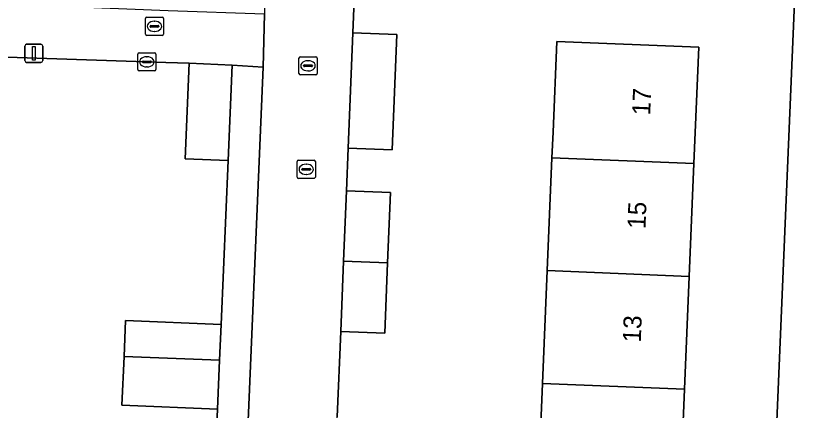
# Model space of a CAD drawing. Extents: x 161354 to 162026, y 386504 to 387460.
# Drawn here: x 161513.06 to 161556.22, y 386723.13 to 386744.88 of the extents above; entities that cross this region are included whole.
import ezdxf

# ---------------------------------------------------------------- set-up
doc = ezdxf.new("R2010")
doc.units = 0
for name, color, linetype in [('IMGEO_Brandkraan', 7, 'Continuous'), ('IMGEO_Erf', 7, 'Continuous'), ('IMGEO_Kolk', 7, 'Continuous'), ('IMGEO_Lichtmast', 7, 'Continuous'), ('IMGEO_Pand', 7, 'Continuous'), ('IMGEO_Pand_nummerreeks', 7, 'Continuous'), ('IMGEO_Rijbaan_lokaal_open', 7, 'Continuous'), ('IMGEO_Rioolput', 7, 'Continuous'), ('IMGEO_Voetpad_open', 7, 'Continuous')]:
    doc.layers.add(name, color=color, linetype=linetype)

msp = doc.modelspace()

# ---------------------------------------------------------------- linework, layer by layer
at = {"layer": 'IMGEO_Brandkraan'}
for p, q in [((161520.21, 386743.865), (161520.21, 386744.717)), ((161520.285, 386744.791), (161521.137, 386744.791)), ((161521.211, 386744.717), (161521.211, 386743.865)), ((161520.469, 386744.285), (161520.469, 386744.297)), ((161520.907, 386744.248), (161520.509, 386744.248)), ((161520.512, 386744.334), (161520.91, 386744.334)), ((161520.698, 386744.571), (161520.723, 386744.571)), ((161520.953, 386744.297), (161520.953, 386744.285)), ((161521.137, 386743.791), (161520.285, 386743.791)), ((161520.721, 386744.011), (161520.696, 386744.011))]:
    msp.add_line(p, q, dxfattribs=at)
for points in [[(161520.21, 386743.865), (161520.21, 386744.717)], [(161520.285, 386744.791), (161521.137, 386744.791)], [(161521.211, 386744.717), (161521.211, 386743.865)], [(161521.137, 386743.791), (161520.285, 386743.791)]]:
    msp.add_lwpolyline(points, dxfattribs=at)
for centre, radius, start, end in [((161520.287, 386744.715), 0.0765, 91.552, 178.448), ((161520.287, 386744.715), 0.0765, 91.552, 178.448), ((161521.135, 386744.715), 0.0765, 1.552, 88.448), ((161521.135, 386744.715), 0.0765, 1.552, 88.448), ((161520.509, 386744.294), 0.0403, 85.8775, 175.7526), ((161520.506, 386744.284), 0.0366, 178.938, 274.7102), ((161520.91, 386744.291), 0.043, 264.8664, 352.4533), ((161520.914, 386744.296), 0.0386, 1.7309, 96.639), ((161520.287, 386743.867), 0.0765, 181.552, 268.448), ((161520.287, 386743.867), 0.0765, 181.552, 268.448), ((161521.135, 386743.867), 0.0765, 271.552, 358.448), ((161521.135, 386743.867), 0.0765, 271.552, 358.448)]:
    msp.add_arc(centre, radius, start, end, dxfattribs=at)
for centre, major_axis, ratio, start_param, end_param in [((161520.697, 386744.291), (-0.387, 0.002), 0.722429, 4.712389, 7.853982), ((161520.722, 386744.291), (-0.39, 0.002), 0.717154, 1.570796, 4.712389)]:
    msp.add_ellipse(centre, major_axis=major_axis, ratio=ratio, start_param=start_param, end_param=end_param, dxfattribs=at)
at = {"layer": 'IMGEO_Erf'}
for points in [[(161553.534, 386686.819), (161556.007, 386745.625), (161531.769, 386746.655), (161531.657, 386743.931), (161534.086, 386743.832), (161533.827, 386737.476), (161531.398, 386737.577), (161531.302, 386735.23), (161533.731, 386735.129), (161533.572, 386731.252), (161533.414, 386727.375), (161530.986, 386727.476), (161530.794, 386722.78)], [(161541.863, 386718.402), (161542.12, 386724.618), (161542.377, 386730.835), (161542.635, 386737.052), (161542.693, 386738.462), (161542.9, 386743.457), (161550.725, 386743.133), (161550.46, 386736.728), (161550.202, 386730.511), (161549.945, 386724.294), (161549.688, 386718.078)], [(161496.538, 386689.04), (161520.399, 386688.074), (161520.597, 386692.953), (161522.87, 386692.861), (161523.157, 386699.22), (161518.043, 386699.418), (161518.138, 386701.89), (161518.218, 386703.953), (161523.332, 386703.755), (161523.69, 386711.288), (161518.532, 386711.505), (161518.637, 386713.996), (161518.724, 386716.073), (161523.882, 386715.856), (161524.182, 386723.194), (161518.919, 386723.421), (161519.035, 386726.105), (161519.121, 386728.084), (161524.383, 386727.857), (161524.785, 386736.896), (161522.407, 386736.993), (161522.622, 386742.251), (161521.337, 386742.294), (161500, 386743.01)]]:
    msp.add_lwpolyline(points, dxfattribs=at)
at = {"layer": 'IMGEO_Kolk'}
for p, q in [((161519.793, 386741.904), (161519.793, 386742.756)), ((161519.868, 386742.83), (161520.72, 386742.83)), ((161520.281, 386742.61), (161520.306, 386742.61)), ((161520.794, 386742.756), (161520.794, 386741.904)), ((161520.052, 386742.324), (161520.052, 386742.336)), ((161520.49, 386742.287), (161520.092, 386742.287)), ((161520.095, 386742.373), (161520.493, 386742.373)), ((161520.536, 386742.336), (161520.536, 386742.324)), ((161520.72, 386741.83), (161519.868, 386741.83)), ((161520.304, 386742.05), (161520.279, 386742.05)), ((161528.658, 386736.911), (161529.51, 386736.911)), ((161528.583, 386735.985), (161528.583, 386736.837)), ((161528.885, 386736.454), (161529.283, 386736.454)), ((161529.071, 386736.691), (161529.096, 386736.691)), ((161529.584, 386736.837), (161529.584, 386735.985)), ((161528.842, 386736.405), (161528.842, 386736.417)), ((161529.28, 386736.368), (161528.882, 386736.368)), ((161529.094, 386736.131), (161529.069, 386736.131)), ((161529.326, 386736.417), (161529.326, 386736.405)), ((161529.51, 386735.911), (161528.658, 386735.911))]:
    msp.add_line(p, q, dxfattribs=at)
for points in [[(161519.793, 386741.904), (161519.793, 386742.756)], [(161519.868, 386742.83), (161520.72, 386742.83)], [(161520.794, 386742.756), (161520.794, 386741.904)], [(161520.72, 386741.83), (161519.868, 386741.83)], [(161528.658, 386736.911), (161529.51, 386736.911)], [(161528.583, 386735.985), (161528.583, 386736.837)], [(161529.584, 386736.837), (161529.584, 386735.985)], [(161529.51, 386735.911), (161528.658, 386735.911)]]:
    msp.add_lwpolyline(points, dxfattribs=at)
for centre, radius, start, end in [((161519.87, 386742.754), 0.0765, 91.552, 178.448), ((161519.87, 386742.754), 0.0765, 91.552, 178.448), ((161520.718, 386742.754), 0.0765, 1.552, 88.448), ((161520.718, 386742.754), 0.0765, 1.552, 88.448), ((161520.092, 386742.333), 0.0403, 85.8775, 175.7526), ((161520.089, 386742.323), 0.0366, 178.938, 274.7102), ((161520.493, 386742.33), 0.043, 264.8664, 352.4533), ((161520.497, 386742.335), 0.0386, 1.7309, 96.639), ((161519.87, 386741.906), 0.0765, 181.552, 268.448), ((161519.87, 386741.906), 0.0765, 181.552, 268.448), ((161520.718, 386741.906), 0.0765, 271.552, 358.448), ((161520.718, 386741.906), 0.0765, 271.552, 358.448), ((161528.66, 386736.835), 0.0765, 91.552, 178.448), ((161528.66, 386736.835), 0.0765, 91.552, 178.448), ((161529.508, 386736.835), 0.0765, 1.552, 88.448), ((161529.508, 386736.835), 0.0765, 1.552, 88.448), ((161528.882, 386736.414), 0.0403, 85.8775, 175.7526), ((161529.287, 386736.416), 0.0386, 1.7309, 96.639), ((161528.879, 386736.404), 0.0366, 178.938, 274.7102), ((161529.283, 386736.411), 0.043, 264.8664, 352.4533), ((161528.66, 386735.987), 0.0765, 181.552, 268.448), ((161528.66, 386735.987), 0.0765, 181.552, 268.448), ((161529.508, 386735.987), 0.0765, 271.552, 358.448), ((161529.508, 386735.987), 0.0765, 271.552, 358.448)]:
    msp.add_arc(centre, radius, start, end, dxfattribs=at)
for centre, major_axis, ratio, start_param, end_param in [((161520.28, 386742.33), (-0.387, 0.002), 0.722429, 4.712389, 7.853982), ((161520.305, 386742.33), (-0.39, 0.002), 0.717154, 1.570796, 4.712389), ((161529.07, 386736.411), (-0.387, 0.002), 0.722429, 4.712389, 7.853982), ((161529.095, 386736.411), (-0.39, 0.002), 0.717154, 1.570796, 4.712389)]:
    msp.add_ellipse(centre, major_axis=major_axis, ratio=ratio, start_param=start_param, end_param=end_param, dxfattribs=at)
at = {"layer": 'IMGEO_Lichtmast'}
for p, q in [((161513.563, 386742.404), (161513.563, 386743.204)), ((161513.563, 386743.204), (161513.563, 386742.404)), ((161513.663, 386743.304), (161514.453, 386743.304)), ((161514.453, 386743.304), (161513.663, 386743.304)), ((161514.553, 386743.204), (161514.553, 386742.404)), ((161514.553, 386742.404), (161514.553, 386743.204)), ((161514.453, 386742.304), (161513.663, 386742.304)), ((161513.663, 386742.304), (161514.453, 386742.304))]:
    msp.add_line(p, q, dxfattribs=at)
msp.add_lwpolyline([(161513.983, 386743.179), (161514.133, 386743.179), (161514.133, 386742.429), (161513.983, 386742.429), (161513.983, 386743.179)], dxfattribs=at)
for centre, start, end in [((161513.663, 386743.204), 90, 180), ((161513.663, 386743.204), 90, 180), ((161514.453, 386743.204), 0, 90), ((161514.453, 386743.204), 360, 90), ((161513.663, 386742.404), 180, 270), ((161513.663, 386742.404), 180, 270), ((161514.453, 386742.404), 270, 0), ((161514.453, 386742.404), 270, 0)]:
    msp.add_arc(centre, 0.1, start, end, dxfattribs=at)
at = {"layer": 'IMGEO_Pand'}
for points in [[(161531.398, 386737.577), (161533.827, 386737.476), (161534.086, 386743.832), (161531.657, 386743.931)], [(161550.46, 386736.728), (161550.725, 386743.133), (161542.9, 386743.457), (161542.693, 386738.462), (161542.635, 386737.052)], [(161522.622, 386742.251), (161522.407, 386736.993), (161524.785, 386736.896), (161525, 386742.154)], [(161550.202, 386730.511), (161550.46, 386736.728), (161542.635, 386737.052), (161542.377, 386730.835)], [(161533.731, 386735.129), (161531.302, 386735.23), (161531.144, 386731.353), (161533.572, 386731.252)], [(161533.572, 386731.252), (161531.144, 386731.353), (161530.986, 386727.476), (161533.414, 386727.375)], [(161542.377, 386730.835), (161542.12, 386724.618), (161549.945, 386724.294), (161550.202, 386730.511)], [(161524.383, 386727.857), (161519.121, 386728.084), (161519.035, 386726.105), (161524.299, 386725.901)], [(161524.299, 386725.901), (161519.035, 386726.105), (161518.919, 386723.421), (161524.182, 386723.194)], [(161549.688, 386718.078), (161549.945, 386724.294), (161542.12, 386724.618), (161541.863, 386718.402)]]:
    msp.add_lwpolyline(points, close=True, dxfattribs=at)
at = {"layer": 'IMGEO_Rijbaan_lokaal_open'}
msp.add_lwpolyline([(161556.221, 386751.504), (161556.166, 386750), (161556.007, 386745.625), (161553.534, 386686.819), (161552.686, 386666.678), (161552.424, 386660.44)], dxfattribs=at)
msp.add_lwpolyline([(161530.636, 386718.903), (161530.794, 386722.78), (161530.986, 386727.476), (161531.144, 386731.353), (161531.302, 386735.23), (161531.398, 386737.577), (161531.657, 386743.931), (161531.769, 386746.655), (161530.64, 386746.711), (161530.713, 386748.117), (161526.871, 386748.302), (161526.786, 386744.962), (161526.711, 386742.045), (161524.41, 386687.933), (161529.439, 386687.685), (161529.461, 386690.128), (161529.619, 386694.005), (161529.778, 386697.882), (161529.97, 386702.578), (161530.128, 386706.455), (161530.286, 386710.332), (161530.478, 386715.026)], close=True, dxfattribs=at)
at = {"layer": 'IMGEO_Rioolput'}
for p, q in [((161528.678, 386741.69), (161528.678, 386742.542)), ((161528.753, 386742.616), (161529.605, 386742.616)), ((161529.679, 386742.542), (161529.679, 386741.69)), ((161528.937, 386742.11), (161528.937, 386742.122)), ((161529.375, 386742.073), (161528.977, 386742.073)), ((161528.98, 386742.159), (161529.378, 386742.159)), ((161529.166, 386742.396), (161529.191, 386742.396)), ((161529.421, 386742.122), (161529.421, 386742.11)), ((161529.189, 386741.836), (161529.164, 386741.836)), ((161529.605, 386741.616), (161528.753, 386741.616))]:
    msp.add_line(p, q, dxfattribs=at)
for points in [[(161528.678, 386741.69), (161528.678, 386742.542)], [(161528.753, 386742.616), (161529.605, 386742.616)], [(161529.679, 386742.542), (161529.679, 386741.69)], [(161529.605, 386741.616), (161528.753, 386741.616)]]:
    msp.add_lwpolyline(points, dxfattribs=at)
for centre, radius, start, end in [((161528.755, 386742.54), 0.0765, 91.552, 178.448), ((161528.755, 386742.54), 0.0765, 91.552, 178.448), ((161529.603, 386742.54), 0.0765, 1.552, 88.448), ((161529.603, 386742.54), 0.0765, 1.552, 88.448), ((161528.977, 386742.119), 0.0403, 85.8775, 175.7526), ((161528.974, 386742.109), 0.0366, 178.938, 274.7102), ((161529.378, 386742.116), 0.043, 264.8664, 352.4533), ((161529.382, 386742.121), 0.0386, 1.7309, 96.639), ((161528.755, 386741.692), 0.0765, 181.552, 268.448), ((161528.755, 386741.692), 0.0765, 181.552, 268.448), ((161529.603, 386741.692), 0.0765, 271.552, 358.448), ((161529.603, 386741.692), 0.0765, 271.552, 358.448)]:
    msp.add_arc(centre, radius, start, end, dxfattribs=at)
for centre, major_axis, ratio, start_param, end_param in [((161529.165, 386742.116), (-0.387, 0.002), 0.722429, 4.712389, 7.853982), ((161529.19, 386742.116), (-0.39, 0.002), 0.717154, 1.570796, 4.712389)]:
    msp.add_ellipse(centre, major_axis=major_axis, ratio=ratio, start_param=start_param, end_param=end_param, dxfattribs=at)
at = {"layer": 'IMGEO_Voetpad_open'}
for points in [[(161526.786, 386744.962), (161521.471, 386745.146), (161500, 386746.032), (161457.697, 386747.778), (161457.628, 386744.231), (161457.951, 386744.227), (161461.324, 386744.185), (161463.187, 386744.162), (161489.514, 386743.133), (161495.194, 386742.911), (161498.722, 386743.053), (161500, 386743.01), (161521.337, 386742.294), (161522.622, 386742.251), (161525, 386742.154), (161526.711, 386742.045)], [(161524.299, 386725.901), (161524.182, 386723.194), (161523.882, 386715.856), (161523.795, 386713.795), (161523.69, 386711.288), (161523.332, 386703.755), (161523.252, 386701.692), (161523.157, 386699.22), (161522.87, 386692.861), (161522.672, 386687.982), (161524.41, 386687.933), (161526.711, 386742.045), (161525, 386742.154), (161524.785, 386736.896), (161524.383, 386727.857)]]:
    msp.add_lwpolyline(points, close=True, dxfattribs=at)

# ---------------------------------------------------------------- texts
at = {"layer": 'IMGEO_Pand_nummerreeks'}
for s, p in [('17', (161548.047, 386739.374)), ('15', (161547.788, 386733.115)), ('13', (161547.529, 386726.856))]:
    msp.add_text(s, height=1, rotation=87.6294, dxfattribs=at).set_placement(p)

doc.saveas('drawing.dxf')
